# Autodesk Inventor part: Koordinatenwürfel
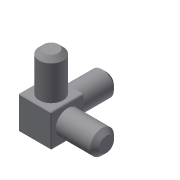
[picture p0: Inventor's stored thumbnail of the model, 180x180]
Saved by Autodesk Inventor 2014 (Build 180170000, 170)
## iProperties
Company: VDW-Nachwuchsstiftung
Created: 2014-04
Part Number: Koordinatenwürfel
Material: Generisch
Document SubType Name: Modeling
Designer: e_dammj
Density: 1 g/cm^3
Appearance: Vorgabe
Author: e_dammj
Title: Koordinatenwürfel
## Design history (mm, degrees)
sketch "Skizze1"
  geometry: L1 (-11, -11)-(11, -11); L2 (11, -11)-(11, 11); L3 (11, 11)-(-11, 11); L4 (-11, 11)-(-11, -11); L5 (-11, -11)-(11, 11); L6 (11, -11)-(-11, 11); 1 further point
  constraints: 12 end point, 2 midpoint, 2 parallel, 1 horizontal, 1 perpendicular
  dimensions: "d0" = 22 distance of L3.end L2.end; "d1" = 22 distance of L2.end L1.end
extrude "Grundkörper" new body sketch "Skizze1" distance "d2" = 22; taper "d3" = 0 deg
sketch "Skizze2"
  geometry: C1 r 8 at (0, 0); 1 further point
  constraints: 1 centre point, 1 coincident
  dimensions: "d4" = 16 diameter of C1
extrude "Extrusion_Z-Achse" join sketch "Skizze2" distance "d5" = 26; taper "d6" = 0 deg
sketch "Skizze3"
  geometry: L1 (0, 0)-(0, 22) reference; L2 (0, 22)-(22, 22) reference; C1 r 8 at (11, 11); 3 further points
  constraints: 2 midpoint, 1 centre point, 1 horizontal alignment, 1 vertical alignment
  dimensions: "d7" = 16 diameter of C1
extrude "Extrusion_X-Achse" join sketch "Skizze3" distance "d8" = 26; taper "d9" = 0 deg
sketch "Skizze4"
  geometry: L1 (22, 0)-(22, 22) reference; L2 (0, 22)-(22, 22) reference; C1 r 8 at (11, 11); 3 further points
  constraints: 2 midpoint, 1 centre point, 1 horizontal alignment, 1 vertical alignment
  dimensions: "d10" = 16 diameter of C1
extrude "Extrusion_Y-Achse" join sketch "Skizze4" distance "d11" = 26; taper "d12" = 0 deg
chamfer "Fase_3 mm" distance "d13" = 3; stored, may be unused: second distance "d14" = 2, angle "d15" = 45 deg
chamfer "Fase_0,5 mm" distance "d16" = 0.5; stored, may be unused: second distance "d17" = 2, angle "d18" = 45 deg
workplane "Arbeitsebene1"
sketch "Skizze5"
  geometry: L1 (26, 5)-(26, -5) reference; 4 further points
  constraints: 2 horizontal alignment, 1 midpoint, 2 other
  dimensions: "d21" = 8 distance from line of L1 point (18, 0); "d28" = 18 distance from line of L1 point (8, 0)
feature "Prägen_X-Achse" sketch "Skizze5" dims "d0" = 22, "d1" = 22, "d22" = 0.05, "d23" = 0
workplane "Arbeitsebene2"
sketch "Skizze6"
  geometry: L1 (-26, -5)-(-26, 5) reference; 4 further points
  constraints: 2 horizontal alignment, 1 midpoint, 2 other
  dimensions: "d24" = 8 distance of point (-26, 0) point (-18, 0); "d25" = 18 distance of point (-26, 0) point (-8, 0)
feature "Prägen_Y-Achse" sketch "Skizze6" dims "d0" = 22, "d1" = 22, "d26" = 0.05, "d27" = 0
workplane "Arbeitsebene3"
sketch "Skizze7"
  geometry: L1 (-5, 26)-(5, 26) reference; 4 further points
  constraints: 2 vertical alignment, 1 midpoint, 2 other
  dimensions: "d29" = 8 distance from line of L1 point (0, 18); "d30" = 18 distance from line of L1 point (0, 8)
feature "Prägen_Z-Achse" sketch "Skizze7" dims "d0" = 22, "d1" = 22, "d31" = 0.05, "d32" = 0
node "Volumenkörper1"
